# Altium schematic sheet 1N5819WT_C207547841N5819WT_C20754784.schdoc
size 127 x 101 mm
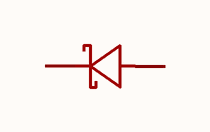
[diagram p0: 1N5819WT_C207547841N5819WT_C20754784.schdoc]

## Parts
D?  1n5819wt_c20754784  [SOD-523_L1.2-W0.8-LS1.6-RD]  (value not drawn)

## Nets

Not connected (* = marked no-connect by the designer): D? 1(A) 2(K)

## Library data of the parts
D? = 1n5819wt_c20754784: 二极管配置:独立式;正向压降(Vf):600mV@200mA;直流反向耐压(Vr):40V;整流电流:350mA;; Manufacturer: JSMSEMI(杰盛微); AddInBom: yes; ModelId: 8f56a03db567494d8f4c9d12aa52a741; ModelName: SOD-523_L1.2-W0.8-H0.7-LS1.6; ModelTransform: 62.992,31.496,0,180,0,0,0,0,0; Diode Configuration: 独立式; Voltage - DC Reverse(Vr): 40V; Current - Rectified: 350mA; Reverse Leakage Current (Ir): 5uA@30V; Non-Repetitive Peak Forward Surge Current: 13A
